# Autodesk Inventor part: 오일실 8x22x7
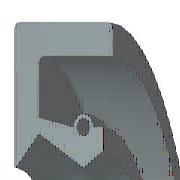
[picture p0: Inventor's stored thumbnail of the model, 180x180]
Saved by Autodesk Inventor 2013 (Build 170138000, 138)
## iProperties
IsCustomPart: 1
Company: 한국ATC센터
Created: 2014-07
Part Number: 오일실 8x22x7
Material: Rubber
Description: 오일-실
Document SubType Name: Modeling
Standard: KS B 2804
Designer: KYOUNG IL JANG
Standards Organization: KS
Language: ko-KR
Size Designation: D - 8 22 7
Categories: <MemberInstance><Categories><Category DisplayName="샤프트 부품" InternalName="7f7aeb1f-a693-4053-b835-cee3144e0d98" Mnemonic="SHFT"><Category DisplayName="실링" Intern
Density: 0.93 g/cm^3
Author: KYOUNG IL JANG
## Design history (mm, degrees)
revolve "본체" stored, may be unused: angle "d17" = 90 deg
revolve "스프링1" stored, may be unused: angle "d18" = 90 deg
body "Solid1"
sketch "스케치1"
  geometry: L1 (0, 11)-(7, 11); L2 (7, 9.25)-(1.75, 9.25); L3 (1.75, 5.75)-(4.9, 4); L4 (4.9, 4)-(0, 4); L5 (0, 0)-(9.586, 0) reference; L6 (4.9, 4)-(6.3, 4.875); L7 (0, 18)-(0, -3) reference; L8 (-1.941, 0)-(11.507, 0) reference; L9 (4.2, 6.1)-(1.75, 6.59); L10 (1.75, 6.59)-(1.75, 9.25); L11 (0, 11)-(0, 4.088); L12 (4.9, 4)-(0, 4); L13 (1.75, 5.75)-(0.152, 4.028); L14 (7, 11)-(7, 9.25); L15 (5.6, 6.1)-(6.3, 6.1); L16 (6.3, 6.1)-(6.3, 4.875); C1 r 0.455 at (4.9, 6.1); A1 r 0.7 centre (4.9, 6.1) between (5.6, 6.1) and (4.2, 6.1); A2 r 0.088 centre (0.088, 4.088) between (0, 4.088) and (0.152, 4.028); 1 further point
  constraints: 28 end point, 5 horizontal alignment, 5 point on line, 4 point on circle, 4 vertical alignment, 3 centre point, 3 tangent, 2 collinear, 2 horizontal, 2 perpendicular, 1 coincident, 1 parallel
  dimensions: "d0" = 22 diameter of L1 L5 (= SD2); "d1" = 1.75 distance of L1.end L2.start (= SD); "d2" = 0.91 diameter of C1 (= SPDI); "d3" = 1.4 diameter of A1 (= SPDA); "d4" = 8 diameter of L3.end L5 (= NND); "d5" = 11.5 diameter of L3.start L5 (= TKDM); "d7" = 13.18 diameter of L9.end L5 (= TKDM + 0.24 x SWDT); "d8" = 1.75 distance between parallel lines of L11 L10 (= SD); "d9" = 4.9 distance from line of L11 C1.centre (= SPDST); "d10" = 12.2 diameter of C1.centre L5 (= HLDM); "d11" = 0.0875 radius of A2 (= 0.25 x LAB); "d12" = 6.3 distance between parallel lines of L11 L16 (= SDI); "d13" = 9.75 diameter of L6.end L5 (= ABDM); "d14" = 7 distance from line of L11 L1.end (= SWDT)
fillet "모깎기1" dims "d6" = 0.3 (= RR)
other parameters: "SD2" = 22 [user parameter; used in 1 equation term], "SWDT" = 7 [user parameter; used in 2 equation terms], "RR" = 0.3 [user parameter; used in 1 equation term], "SD" = 1.75 [user parameter; used in 2 equation terms], "NND" = 8 [user parameter; used in 1 equation term], "SPDA" = 1.4 [user parameter; used in 1 equation term], "SPDI" = 0.91 [user parameter; used in 1 equation term], "TKDM" = 11.5 [user parameter; used in 2 equation terms], "HLDM" = 12.2 [user parameter; used in 1 equation term], "ABDM" = 9.75 [user parameter; used in 1 equation term], "SDI" = 6.3 [user parameter; used in 1 equation term], "SPDST" = 4.9 [user parameter; used in 1 equation term], "LAB" = 0.35 [user parameter; used in 1 equation term], "d15" = 0, "d16" = 0, "d19" = 0
